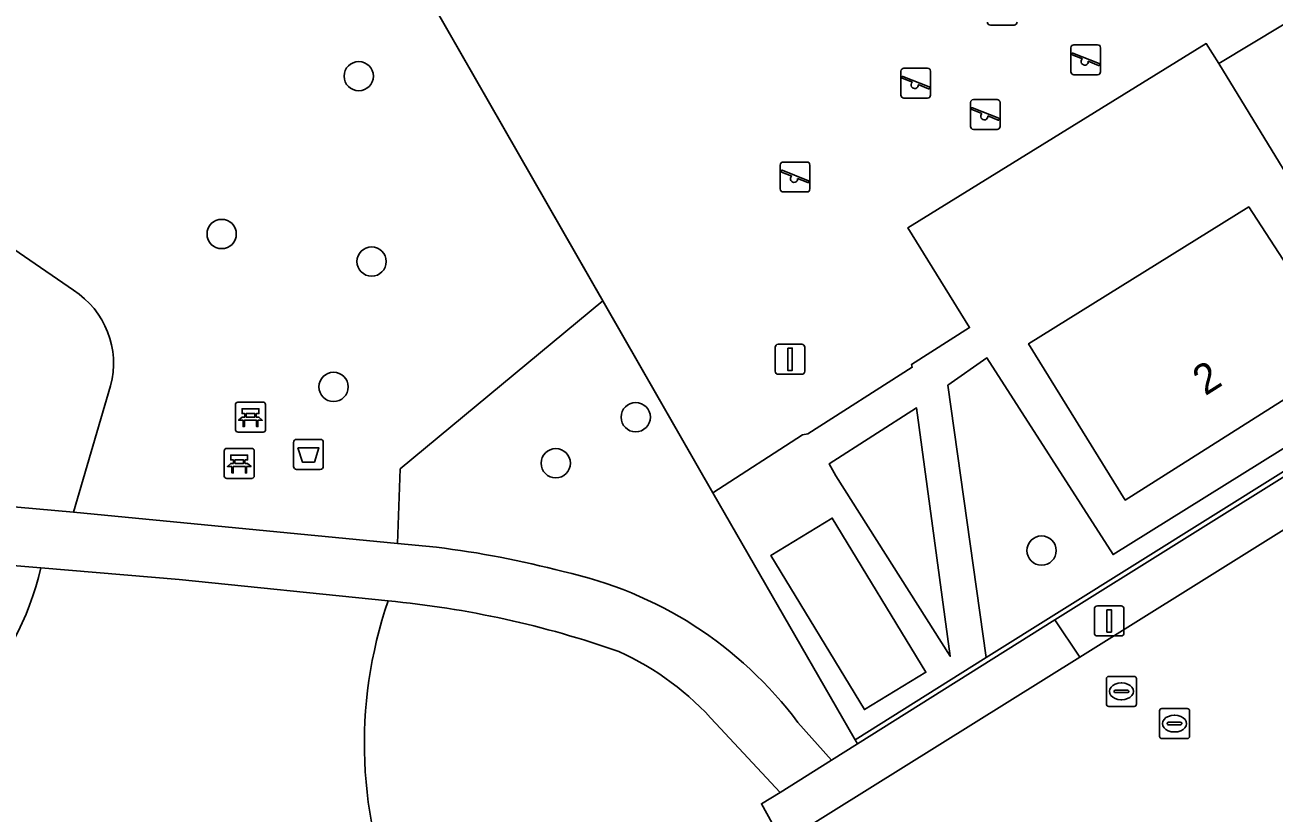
# Model space of a CAD drawing. Extents: x 159664 to 160323, y 385312 to 386115.
# Drawn here: x 159905.94 to 159947.68, y 385725.69 to 385752 of the extents above; entities that cross this region are included whole.
import ezdxf

# ---------------------------------------------------------------- set-up
doc = ezdxf.new("R2010")
doc.units = 0
for name, color, linetype in [('IMGEO_Afvalbak', 7, 'Continuous'), ('IMGEO_Bank', 7, 'Continuous'), ('IMGEO_Boom', 7, 'Continuous'), ('IMGEO_Groenvoorziening', 7, 'Continuous'), ('IMGEO_Hek', 7, 'Continuous'), ('IMGEO_Lichtmast', 7, 'Continuous'), ('IMGEO_Pand', 7, 'Continuous'), ('IMGEO_Pand_nummerreeks', 7, 'Continuous'), ('IMGEO_Rijbaan_lokaal_open', 7, 'Continuous'), ('IMGEO_Rioolput', 7, 'Continuous'), ('IMGEO_Speelvoorziening', 7, 'Continuous'), ('IMGEO_Terreindeel_zand', 7, 'Continuous'), ('IMGEO_Vlaggenmast', 7, 'Continuous'), ('IMGEO_Voetpad_halfverhard', 7, 'Continuous'), ('IMGEO_Voetpad_open', 7, 'Continuous')]:
    doc.layers.add(name, color=color, linetype=linetype)

msp = doc.modelspace()

# ---------------------------------------------------------------- linework, layer by layer
at = {"layer": 'IMGEO_Afvalbak'}
for p, q in [((159914.908, 385737.266), (159914.908, 385738.066)), ((159914.908, 385738.066), (159914.908, 385737.266)), ((159915.008, 385738.166), (159915.798, 385738.166)), ((159915.798, 385738.166), (159915.008, 385738.166)), ((159915.898, 385738.066), (159915.898, 385737.266)), ((159915.898, 385737.266), (159915.898, 385738.066)), ((159915.798, 385737.166), (159915.008, 385737.166)), ((159915.008, 385737.166), (159915.798, 385737.166))]:
    msp.add_line(p, q, dxfattribs=at)
msp.add_lwpolyline([(159915.051, 385737.88), (159915.755, 385737.88), (159915.606, 385737.41), (159915.2, 385737.41), (159915.051, 385737.88)], dxfattribs=at)
for centre, start, end in [((159915.008, 385738.066), 90, 180), ((159915.008, 385738.066), 90, 180), ((159915.798, 385738.066), 0, 90), ((159915.798, 385738.066), 360, 90), ((159915.008, 385737.266), 180, 270), ((159915.008, 385737.266), 180, 270), ((159915.798, 385737.266), 270, 0), ((159915.798, 385737.266), 270, 0)]:
    msp.add_arc(centre, 0.1, start, end, dxfattribs=at)
at = {"layer": 'IMGEO_Bank'}
for p, q in [((159912.969, 385738.484), (159912.969, 385739.325)), ((159912.969, 385739.325), (159912.969, 385738.484)), ((159913.044, 385739.409), (159913.885, 385739.409)), ((159913.885, 385739.409), (159913.044, 385739.409)), ((159913.969, 385739.334), (159913.969, 385738.493)), ((159913.969, 385738.493), (159913.969, 385739.334)), ((159913.666, 385738.807), (159913.273, 385738.807)), ((159913.278, 385738.915), (159913.278, 385739.021)), ((159913.322, 385739.021), (159913.322, 385738.915)), ((159913.61, 385739.027), (159913.328, 385739.027)), ((159913.328, 385738.909), (159913.61, 385738.909)), ((159913.616, 385738.915), (159913.616, 385739.021)), ((159913.66, 385739.021), (159913.66, 385738.915)), ((159913.894, 385738.409), (159913.053, 385738.409)), ((159913.053, 385738.409), (159913.894, 385738.409)), ((159912.594, 385736.94), (159912.594, 385737.781)), ((159912.594, 385737.781), (159912.594, 385736.94)), ((159912.669, 385737.865), (159913.51, 385737.865)), ((159913.51, 385737.865), (159912.669, 385737.865)), ((159913.594, 385737.79), (159913.594, 385736.949)), ((159913.594, 385736.949), (159913.594, 385737.79)), ((159913.291, 385737.263), (159912.898, 385737.263)), ((159912.903, 385737.371), (159912.903, 385737.477)), ((159912.947, 385737.477), (159912.947, 385737.371)), ((159913.235, 385737.483), (159912.953, 385737.483)), ((159912.953, 385737.365), (159913.235, 385737.365)), ((159913.241, 385737.371), (159913.241, 385737.477)), ((159913.285, 385737.477), (159913.285, 385737.371)), ((159913.519, 385736.865), (159912.678, 385736.865)), ((159912.678, 385736.865), (159913.519, 385736.865))]:
    msp.add_line(p, q, dxfattribs=at)
for points in [[(159913.272, 385739.027), (159913.186, 385739.027), (159913.186, 385739.188), (159913.749, 385739.188), (159913.749, 385739.027), (159913.666, 385739.027)], [(159913.216, 385738.807), (159913.074, 385738.807), (159913.186, 385738.909), (159913.272, 385738.909)], [(159913.266, 385738.8), (159913.266, 385738.593), (159913.223, 385738.593), (159913.223, 385738.8)], [(159913.666, 385738.909), (159913.749, 385738.909), (159913.861, 385738.807), (159913.722, 385738.807)], [(159913.716, 385738.8), (159913.716, 385738.593), (159913.672, 385738.593), (159913.672, 385738.8)], [(159912.897, 385737.483), (159912.811, 385737.483), (159912.811, 385737.644), (159913.374, 385737.644), (159913.374, 385737.483), (159913.291, 385737.483)], [(159912.841, 385737.263), (159912.699, 385737.263), (159912.811, 385737.365), (159912.897, 385737.365)], [(159912.891, 385737.256), (159912.891, 385737.049), (159912.848, 385737.049), (159912.848, 385737.256)], [(159913.291, 385737.365), (159913.374, 385737.365), (159913.486, 385737.263), (159913.347, 385737.263)], [(159913.341, 385737.256), (159913.341, 385737.049), (159913.297, 385737.049), (159913.297, 385737.256)]]:
    msp.add_lwpolyline(points, dxfattribs=at)
for centre, radius, start, end in [((159913.047, 385739.331), 0.0779, 92.4484, 184.2845), ((159913.047, 385739.331), 0.0779, 92.4484, 184.2845), ((159913.891, 385739.331), 0.0779, 2.4484, 94.2845), ((159913.891, 385739.331), 0.0779, 2.4484, 94.2845), ((159913.216, 385738.8), 0.00671, 2.8957, 87.1043), ((159913.273, 385738.8), 0.00671, 92.8957, 177.1043), ((159913.271, 385739.02), 0.00671, 2.8957, 87.1043), ((159913.271, 385738.916), 0.00671, 272.8957, 357.1043), ((159913.328, 385739.02), 0.00671, 92.8957, 177.1043), ((159913.328, 385738.916), 0.00671, 182.8957, 267.1043), ((159913.61, 385739.02), 0.00671, 2.8957, 87.1043), ((159913.61, 385738.916), 0.00671, 272.8957, 357.1043), ((159913.667, 385739.02), 0.00671, 92.8957, 177.1043), ((159913.667, 385738.916), 0.00671, 182.8957, 267.1043), ((159913.665, 385738.8), 0.00671, 2.8957, 87.1043), ((159913.722, 385738.8), 0.00671, 92.8957, 177.1043), ((159913.047, 385738.487), 0.0779, 182.4484, 274.2845), ((159913.047, 385738.487), 0.0779, 182.4484, 274.2845), ((159913.891, 385738.487), 0.0779, 272.4484, 4.2845), ((159913.891, 385738.487), 0.0779, 272.4484, 4.2845), ((159912.672, 385737.787), 0.0779, 92.4484, 184.2845), ((159912.672, 385737.787), 0.0779, 92.4484, 184.2845), ((159913.516, 385737.787), 0.0779, 2.4484, 94.2845), ((159913.516, 385737.787), 0.0779, 2.4484, 94.2845), ((159912.841, 385737.256), 0.00671, 2.8957, 87.1043), ((159912.898, 385737.256), 0.00671, 92.8957, 177.1043), ((159912.896, 385737.476), 0.00671, 2.8957, 87.1043), ((159912.896, 385737.372), 0.00671, 272.8957, 357.1043), ((159912.953, 385737.476), 0.00671, 92.8957, 177.1043), ((159912.953, 385737.372), 0.00671, 182.8957, 267.1043), ((159913.235, 385737.476), 0.00671, 2.8957, 87.1043), ((159913.235, 385737.372), 0.00671, 272.8957, 357.1043), ((159913.292, 385737.476), 0.00671, 92.8957, 177.1043), ((159913.292, 385737.372), 0.00671, 182.8957, 267.1043), ((159913.29, 385737.256), 0.00671, 2.8957, 87.1043), ((159913.347, 385737.256), 0.00671, 92.8957, 177.1043), ((159912.672, 385736.943), 0.0779, 182.4484, 274.2845), ((159912.672, 385736.943), 0.0779, 182.4484, 274.2845), ((159913.516, 385736.943), 0.0779, 272.4484, 4.2845), ((159913.516, 385736.943), 0.0779, 272.4484, 4.2845)]:
    msp.add_arc(centre, radius, start, end, dxfattribs=at)
at = {"layer": 'IMGEO_Boom'}
for centre in [(159917.083, 385750.296), (159912.506, 385745.025), (159917.514, 385744.106), (159916.242, 385739.919), (159926.331, 385738.908), (159923.662, 385737.37), (159939.883, 385734.452)]:
    msp.add_circle(centre, 0.489, dxfattribs=at)
at = {"layer": 'IMGEO_Groenvoorziening'}
for points in [[(159964.674, 385816.154), (159964.662, 385816.146), (159915.717, 385785.521), (159915.048, 385785.102), (159909.031, 385781.344), (159908.899, 385778.308), (159910.953, 385779.54), (159909.705, 385781.51), (159964.547, 385815.857), (159975.15, 385798.647), (159995.344, 385766.743), (159938.039, 385730.88), (159933.655, 385728.136), (159933.737, 385727.999), (159940.323, 385732.142), (159995.631, 385766.698)], [(159933.011, 385736.953), (159936.833, 385730.926), (159935.712, 385739.216), (159932.794, 385737.352)]]:
    msp.add_lwpolyline(points, close=True, dxfattribs=at)
for points in [[(159964.547, 385815.857), (159909.705, 385781.51), (159910.953, 385779.54), (159908.899, 385778.308), (159908.939, 385771.242), (159914.881, 385760.864), (159925.232, 385742.788), (159928.903, 385736.377), (159931.906, 385738.317), (159932.08, 385738.352), (159935.567, 385740.576), (159935.542, 385740.668), (159937.481, 385741.9), (159935.42, 385745.233), (159945.381, 385751.383), (159945.799, 385750.719), (159955.225, 385756.405)], [(159952.155, 385740.478), (159942.271, 385734.319), (159938.056, 385740.887), (159936.758, 385739.975), (159938.039, 385730.88), (159995.344, 385766.743)], [(159996.196, 385765.779), (159995.631, 385766.698), (159940.323, 385732.142), (159941.158, 385730.896), (159952.576, 385738.028), (159993.896, 385763.849)], [(159908.795, 385739.955), (159907.564, 385735.733), (159918.383, 385734.689), (159918.469, 385737.182), (159925.232, 385742.788), (159914.881, 385760.864)], [(159904.334, 385748.672), (159903.064, 385746.029), (159904.102, 385745.522), (159907.555, 385743.146)], [(159907.555, 385743.146), (159904.102, 385745.522), (159903.064, 385746.029), (159899.059, 385737.501)], [(159925.232, 385742.788), (159918.469, 385737.182), (159918.383, 385734.689), (159919.683, 385734.564)], [(159931.746, 385728.713), (159932.866, 385727.451), (159933.737, 385727.999), (159933.655, 385728.136), (159933.623, 385728.192), (159928.903, 385736.377), (159925.232, 385742.788)], [(159900.067, 385736.408), (159907.564, 385735.733), (159908.795, 385739.955)], [(159906.469, 385733.876), (159898.351, 385734.556)], [(159918.065, 385732.775), (159911.086, 385733.49), (159906.469, 385733.876)], [(159918.505, 385722.118), (159908.69, 385715.673), (159910.716, 385711.901), (159931.246, 385724.705), (159930.531, 385725.997), (159931.155, 385726.375), (159929.003, 385728.681)]]:
    msp.add_lwpolyline(points, dxfattribs=at)
for centre, radius, start, end in [((159906.003, 385740.707), 2.891, 344.932, 57.5396), ((159906.003, 385740.707), 2.891, 344.932, 57.5396), ((159915.99, 385704.035), 30.751, 75.0816, 83.1031), ((159896.906, 385736.103), 9.819, 287.1647, 346.8886), ((159896.906, 385736.103), 9.819, 287.1647, 346.8886), ((159921.138, 385720.823), 13.22, 36.6424, 77.9116), ((159931.967, 385728.011), 14.695, 161.0852, 203.6433), ((159931.967, 385728.011), 14.695, 161.0852, 203.6433), ((159914.958, 385700.247), 32.676, 70.6749, 84.5432), ((159921.788, 385722.345), 9.602, 41.2897, 65.4942)]:
    msp.add_arc(centre, radius, start, end, dxfattribs=at)
at = {"layer": 'IMGEO_Hek'}
msp.add_lwpolyline([(159928.903, 385736.377), (159914.881, 385760.864), (159908.939, 385771.242), (159908.899, 385778.308)], dxfattribs=at)
at = {"layer": 'IMGEO_Lichtmast'}
for p, q in [((159941.646, 385731.704), (159941.646, 385732.504)), ((159941.646, 385732.504), (159941.646, 385731.704)), ((159941.746, 385732.604), (159942.536, 385732.604)), ((159942.536, 385732.604), (159941.746, 385732.604)), ((159942.636, 385732.504), (159942.636, 385731.704)), ((159942.636, 385731.704), (159942.636, 385732.504)), ((159942.536, 385731.604), (159941.746, 385731.604)), ((159941.746, 385731.604), (159942.536, 385731.604))]:
    msp.add_line(p, q, dxfattribs=at)
msp.add_lwpolyline([(159942.066, 385732.479), (159942.216, 385732.479), (159942.216, 385731.729), (159942.066, 385731.729), (159942.066, 385732.479)], dxfattribs=at)
for centre, start, end in [((159941.746, 385732.504), 90, 180), ((159941.746, 385732.504), 90, 180), ((159942.536, 385732.504), 0, 90), ((159942.536, 385732.504), 360, 90), ((159941.746, 385731.704), 180, 270), ((159941.746, 385731.704), 180, 270), ((159942.536, 385731.704), 270, 0), ((159942.536, 385731.704), 270, 0)]:
    msp.add_arc(centre, 0.1, start, end, dxfattribs=at)
at = {"layer": 'IMGEO_Pand'}
for points in [[(159946.801, 385745.931), (159939.452, 385741.359), (159942.678, 385736.138), (159950.11, 385740.844)], [(159930.844, 385734.294), (159933.969, 385729.144), (159936.021, 385730.389), (159932.896, 385735.539)]]:
    msp.add_lwpolyline(points, close=True, dxfattribs=at)
at = {"layer": 'IMGEO_Rijbaan_lokaal_open'}
msp.add_lwpolyline([(159952.673, 385732.726), (159954.961, 385734.193), (159952.576, 385738.028), (159941.158, 385730.896), (159931.727, 385725.005), (159934.102, 385721.187), (159935.571, 385722.098)], dxfattribs=at)
at = {"layer": 'IMGEO_Rioolput'}
for p, q in [((159942.05, 385729.326), (159942.05, 385730.178)), ((159942.125, 385730.252), (159942.977, 385730.252)), ((159942.538, 385730.032), (159942.563, 385730.032)), ((159943.051, 385730.178), (159943.051, 385729.326)), ((159942.309, 385729.746), (159942.309, 385729.758)), ((159942.747, 385729.709), (159942.349, 385729.709)), ((159942.352, 385729.795), (159942.75, 385729.795)), ((159942.793, 385729.758), (159942.793, 385729.746)), ((159942.977, 385729.252), (159942.125, 385729.252)), ((159942.561, 385729.472), (159942.536, 385729.472)), ((159943.898, 385729.175), (159944.75, 385729.175)), ((159943.823, 385728.249), (159943.823, 385729.101)), ((159944.311, 385728.955), (159944.336, 385728.955)), ((159944.824, 385729.101), (159944.824, 385728.249)), ((159944.082, 385728.669), (159944.082, 385728.681)), ((159944.52, 385728.632), (159944.122, 385728.632)), ((159944.125, 385728.718), (159944.523, 385728.718)), ((159944.334, 385728.395), (159944.309, 385728.395)), ((159944.566, 385728.681), (159944.566, 385728.669)), ((159944.75, 385728.175), (159943.898, 385728.175))]:
    msp.add_line(p, q, dxfattribs=at)
for points in [[(159942.05, 385729.326), (159942.05, 385730.178)], [(159942.125, 385730.252), (159942.977, 385730.252)], [(159943.051, 385730.178), (159943.051, 385729.326)], [(159942.977, 385729.252), (159942.125, 385729.252)], [(159943.898, 385729.175), (159944.75, 385729.175)], [(159943.823, 385728.249), (159943.823, 385729.101)], [(159944.824, 385729.101), (159944.824, 385728.249)], [(159944.75, 385728.175), (159943.898, 385728.175)]]:
    msp.add_lwpolyline(points, dxfattribs=at)
for centre, radius, start, end in [((159942.127, 385730.176), 0.0765, 91.552, 178.448), ((159942.127, 385730.176), 0.0765, 91.552, 178.448), ((159942.975, 385730.176), 0.0765, 1.552, 88.448), ((159942.975, 385730.176), 0.0765, 1.552, 88.448), ((159942.349, 385729.755), 0.0403, 85.8775, 175.7526), ((159942.346, 385729.745), 0.0366, 178.938, 274.7102), ((159942.75, 385729.752), 0.043, 264.8664, 352.4533), ((159942.754, 385729.757), 0.0386, 1.7309, 96.639), ((159942.127, 385729.328), 0.0765, 181.552, 268.448), ((159942.127, 385729.328), 0.0765, 181.552, 268.448), ((159942.975, 385729.328), 0.0765, 271.552, 358.448), ((159942.975, 385729.328), 0.0765, 271.552, 358.448), ((159943.9, 385729.099), 0.0765, 91.552, 178.448), ((159943.9, 385729.099), 0.0765, 91.552, 178.448), ((159944.748, 385729.099), 0.0765, 1.552, 88.448), ((159944.748, 385729.099), 0.0765, 1.552, 88.448), ((159944.122, 385728.678), 0.0403, 85.8775, 175.7526), ((159944.119, 385728.668), 0.0366, 178.938, 274.7102), ((159944.523, 385728.675), 0.043, 264.8664, 352.4533), ((159944.527, 385728.68), 0.0386, 1.7309, 96.639), ((159943.9, 385728.251), 0.0765, 181.552, 268.448), ((159943.9, 385728.251), 0.0765, 181.552, 268.448), ((159944.748, 385728.251), 0.0765, 271.552, 358.448), ((159944.748, 385728.251), 0.0765, 271.552, 358.448)]:
    msp.add_arc(centre, radius, start, end, dxfattribs=at)
for centre, major_axis, ratio, start_param, end_param in [((159942.537, 385729.752), (-0.387, 0.002), 0.722429, 4.712389, 7.853982), ((159942.562, 385729.752), (-0.39, 0.002), 0.717154, 1.570796, 4.712389), ((159944.31, 385728.675), (-0.387, 0.002), 0.722429, 4.712389, 7.853982), ((159944.335, 385728.675), (-0.39, 0.002), 0.717154, 1.570796, 4.712389)]:
    msp.add_ellipse(centre, major_axis=major_axis, ratio=ratio, start_param=start_param, end_param=end_param, dxfattribs=at)
at = {"layer": 'IMGEO_Speelvoorziening'}
for p, q in [((159938.964, 385752.004), (159938.174, 385752.004)), ((159938.174, 385752.004), (159938.964, 385752.004)), ((159940.963, 385751.344), (159941.753, 385751.344)), ((159941.753, 385751.344), (159940.963, 385751.344)), ((159940.863, 385750.444), (159940.863, 385751.244)), ((159940.863, 385751.244), (159940.863, 385750.444)), ((159941.246, 385750.872), (159940.907, 385751.009)), ((159940.932, 385751.069), (159941.808, 385750.716)), ((159941.853, 385751.244), (159941.853, 385750.444)), ((159941.853, 385750.444), (159941.853, 385751.244)), ((159935.187, 385749.663), (159935.187, 385750.463)), ((159935.187, 385750.463), (159935.187, 385749.663)), ((159935.287, 385750.563), (159936.077, 385750.563)), ((159936.077, 385750.563), (159935.287, 385750.563)), ((159936.177, 385750.463), (159936.177, 385749.663)), ((159936.177, 385749.663), (159936.177, 385750.463)), ((159941.784, 385750.656), (159941.444, 385750.793)), ((159935.57, 385750.091), (159935.231, 385750.228)), ((159935.256, 385750.288), (159936.132, 385749.935)), ((159941.753, 385750.344), (159940.963, 385750.344)), ((159940.963, 385750.344), (159941.753, 385750.344)), ((159936.108, 385749.875), (159935.768, 385750.012)), ((159936.077, 385749.563), (159935.287, 385749.563)), ((159935.287, 385749.563), (159936.077, 385749.563)), ((159937.51, 385748.618), (159937.51, 385749.418)), ((159937.51, 385749.418), (159937.51, 385748.618)), ((159937.893, 385749.046), (159937.554, 385749.183)), ((159937.579, 385749.243), (159938.455, 385748.89)), ((159937.61, 385749.518), (159938.4, 385749.518)), ((159938.4, 385749.518), (159937.61, 385749.518)), ((159938.5, 385749.418), (159938.5, 385748.618)), ((159938.5, 385748.618), (159938.5, 385749.418)), ((159938.431, 385748.83), (159938.091, 385748.967)), ((159938.4, 385748.518), (159937.61, 385748.518)), ((159937.61, 385748.518), (159938.4, 385748.518)), ((159931.158, 385746.528), (159931.158, 385747.328)), ((159931.158, 385747.328), (159931.158, 385746.528)), ((159931.541, 385746.956), (159931.202, 385747.093)), ((159931.227, 385747.153), (159932.103, 385746.8)), ((159931.258, 385747.428), (159932.048, 385747.428)), ((159932.048, 385747.428), (159931.258, 385747.428)), ((159932.148, 385747.328), (159932.148, 385746.528)), ((159932.148, 385746.528), (159932.148, 385747.328)), ((159932.079, 385746.74), (159931.739, 385746.877)), ((159932.048, 385746.428), (159931.258, 385746.428)), ((159931.258, 385746.428), (159932.048, 385746.428))]:
    msp.add_line(p, q, dxfattribs=at)
for centre, radius, start, end in [((159938.174, 385752.104), 0.1, 180, 270), ((159938.174, 385752.104), 0.1, 180, 270), ((159938.964, 385752.104), 0.1, 270, 0), ((159938.964, 385752.104), 0.1, 270, 0), ((159940.963, 385751.244), 0.1, 90, 180), ((159940.963, 385751.244), 0.1, 90, 180), ((159941.753, 385751.244), 0.1, 0, 90), ((159941.753, 385751.244), 0.1, 360, 90), ((159940.92, 385751.039), 0.0327, 68.078, 248.078), ((159941.325, 385750.782), 0.12, 130.9928, 5.1632), ((159935.287, 385750.463), 0.1, 90, 180), ((159935.287, 385750.463), 0.1, 90, 180), ((159936.077, 385750.463), 0.1, 0, 90), ((159936.077, 385750.463), 0.1, 360, 90), ((159940.963, 385750.444), 0.1, 180, 270), ((159940.963, 385750.444), 0.1, 180, 270), ((159941.753, 385750.444), 0.1, 270, 0), ((159941.753, 385750.444), 0.1, 270, 0), ((159941.796, 385750.686), 0.0327, 248.078, 68.078), ((159935.244, 385750.258), 0.0327, 68.078, 248.078), ((159935.649, 385750.001), 0.12, 130.9928, 5.1632), ((159935.287, 385749.663), 0.1, 180, 270), ((159935.287, 385749.663), 0.1, 180, 270), ((159936.077, 385749.663), 0.1, 270, 0), ((159936.077, 385749.663), 0.1, 270, 0), ((159936.12, 385749.905), 0.0327, 248.078, 68.078), ((159937.61, 385749.418), 0.1, 90, 180), ((159937.61, 385749.418), 0.1, 90, 180), ((159937.567, 385749.213), 0.0327, 68.078, 248.078), ((159938.4, 385749.418), 0.1, 0, 90), ((159938.4, 385749.418), 0.1, 360, 90), ((159937.972, 385748.956), 0.12, 130.9928, 5.1632), ((159938.443, 385748.86), 0.0327, 248.078, 68.078), ((159937.61, 385748.618), 0.1, 180, 270), ((159937.61, 385748.618), 0.1, 180, 270), ((159938.4, 385748.618), 0.1, 270, 0), ((159938.4, 385748.618), 0.1, 270, 0), ((159931.258, 385747.328), 0.1, 90, 180), ((159931.258, 385747.328), 0.1, 90, 180), ((159931.215, 385747.123), 0.0327, 68.078, 248.078), ((159932.048, 385747.328), 0.1, 0, 90), ((159932.048, 385747.328), 0.1, 360, 90), ((159931.62, 385746.866), 0.12, 130.9928, 5.1632), ((159932.091, 385746.77), 0.0327, 248.078, 68.078), ((159931.258, 385746.528), 0.1, 180, 270), ((159931.258, 385746.528), 0.1, 180, 270), ((159932.048, 385746.528), 0.1, 270, 0), ((159932.048, 385746.528), 0.1, 270, 0)]:
    msp.add_arc(centre, radius, start, end, dxfattribs=at)
at = {"layer": 'IMGEO_Terreindeel_zand'}
msp.add_lwpolyline([(159945.799, 385750.719), (159949.972, 385743.889), (159959.078, 385749.211), (159955.225, 385756.405)], close=True, dxfattribs=at)
at = {"layer": 'IMGEO_Vlaggenmast'}
for p, q in [((159931.087, 385741.342), (159931.877, 385741.342)), ((159931.877, 385741.342), (159931.087, 385741.342)), ((159930.987, 385740.442), (159930.987, 385741.242)), ((159930.987, 385741.242), (159930.987, 385740.442)), ((159931.977, 385741.242), (159931.977, 385740.442)), ((159931.977, 385740.442), (159931.977, 385741.242)), ((159931.877, 385740.342), (159931.087, 385740.342)), ((159931.087, 385740.342), (159931.877, 385740.342))]:
    msp.add_line(p, q, dxfattribs=at)
msp.add_lwpolyline([(159931.407, 385741.217), (159931.557, 385741.217), (159931.557, 385740.467), (159931.407, 385740.467), (159931.407, 385741.217)], dxfattribs=at)
for centre, start, end in [((159931.087, 385741.242), 90, 180), ((159931.087, 385741.242), 90, 180), ((159931.877, 385741.242), 0, 90), ((159931.877, 385741.242), 360, 90), ((159931.087, 385740.442), 180, 270), ((159931.087, 385740.442), 180, 270), ((159931.877, 385740.442), 270, 0), ((159931.877, 385740.442), 270, 0)]:
    msp.add_arc(centre, 0.1, start, end, dxfattribs=at)
at = {"layer": 'IMGEO_Voetpad_halfverhard'}
for points in [[(159919.683, 385734.564), (159918.383, 385734.689), (159907.564, 385735.733), (159900.067, 385736.408)], [(159898.351, 385734.556), (159906.469, 385733.876), (159911.086, 385733.49), (159918.065, 385732.775)], [(159929.003, 385728.681), (159931.155, 385726.375), (159932.866, 385727.451), (159931.746, 385728.713)]]:
    msp.add_lwpolyline(points, dxfattribs=at)
for centre, radius, start, end in [((159915.99, 385704.035), 30.751, 75.0816, 83.1031), ((159921.138, 385720.823), 13.22, 36.6424, 77.9116), ((159914.958, 385700.247), 32.676, 70.6749, 84.5432), ((159921.788, 385722.345), 9.602, 41.2897, 65.4942)]:
    msp.add_arc(centre, radius, start, end, dxfattribs=at)
at = {"layer": 'IMGEO_Voetpad_open'}
for points in [[(159952.155, 385740.478), (159949.972, 385743.889), (159945.799, 385750.719), (159945.381, 385751.383), (159935.42, 385745.233), (159937.481, 385741.9), (159935.542, 385740.668), (159935.567, 385740.576), (159932.08, 385738.352), (159931.906, 385738.317), (159928.903, 385736.377), (159933.623, 385728.192), (159933.655, 385728.136), (159938.039, 385730.88), (159936.758, 385739.975), (159938.056, 385740.887), (159942.271, 385734.319)], [(159939.452, 385741.359), (159946.801, 385745.931), (159950.11, 385740.844), (159942.678, 385736.138)], [(159936.833, 385730.926), (159933.011, 385736.953), (159932.794, 385737.352), (159935.712, 385739.216)], [(159936.021, 385730.389), (159933.969, 385729.144), (159930.844, 385734.294), (159932.896, 385735.539)], [(159941.158, 385730.896), (159940.323, 385732.142), (159933.737, 385727.999), (159932.866, 385727.451), (159931.155, 385726.375), (159930.531, 385725.997), (159931.246, 385724.705), (159931.727, 385725.005)]]:
    msp.add_lwpolyline(points, close=True, dxfattribs=at)

# ---------------------------------------------------------------- texts
at = {"layer": 'IMGEO_Pand_nummerreeks'}
msp.add_text('2', height=1, rotation=32.3435, dxfattribs=at).set_placement((159945.347, 385739.603))

doc.saveas('drawing.dxf')
